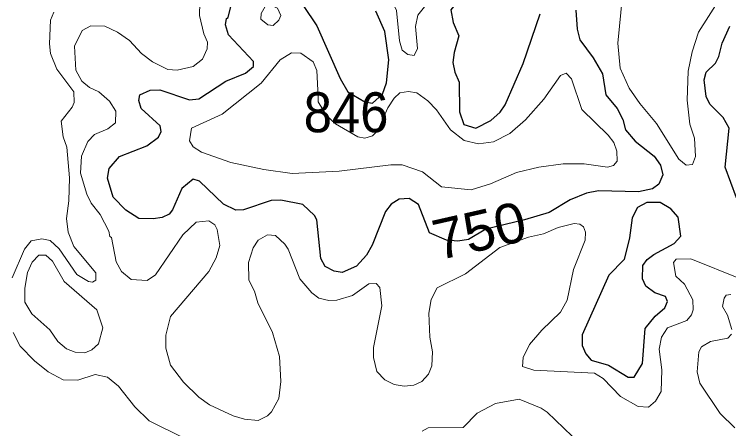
# Model space of a CAD drawing. Extents: x 763.2 to 816.8, y 7896.5 to 7952.7.
# Drawn here: x 783.297 to 786.157, y 7921.048 to 7922.705 of the extents above; entities that cross this region are included whole.
import ezdxf
from ezdxf.enums import TextEntityAlignment as Align

# ---------------------------------------------------------------- set-up
doc = ezdxf.new("R2010")
doc.units = 0
doc.header["$LTSCALE"] = 0.064
doc.layers.add('1', color=7, linetype='Continuous', lineweight=25)
doc.layers.add('2', color=7, linetype='Continuous', lineweight=13)
doc.layers.add('21', color=7, linetype='Continuous')
doc.layers.add('61', color=7, linetype='Continuous')

msp = doc.modelspace()

# ---------------------------------------------------------------- linework, layer by layer
at = {"layer": '1'}
for points in [[(784.5082, 7921.8828), (784.4988, 7921.9003), (784.4517, 7921.9437), (784.3646, 7921.9615), (784.3262, 7921.9601), (784.2144, 7921.923), (784.1847, 7921.9208), (784.1344, 7921.9449), (784.0391, 7922.0369), (784.0137, 7922.045), (783.9686, 7922.0075), (783.9307, 7921.9224), (783.9175, 7921.9053), (783.8888, 7921.8923), (783.8536, 7921.8862), (783.7953, 7921.888), (783.7437, 7921.9213), (783.6931, 7921.9741), (783.6703, 7922.0495), (783.6774, 7922.0887), (783.7181, 7922.1357), (783.828, 7922.1787), (783.8751, 7922.2129), (783.8854, 7922.2362), (783.8811, 7922.2593), (783.8049, 7922.3275), (783.7953, 7922.3598), (783.8001, 7922.3822), (783.8413, 7922.4019), (783.8799, 7922.4021), (783.999, 7922.3629), (784.0358, 7922.3671), (784.1437, 7922.4373), (784.2224, 7922.4697), (784.2552, 7922.4957), (784.2552, 7922.5164), (784.1548, 7922.6226), (784.1422, 7922.6627), (784.1469, 7922.6884), (784.1534, 7922.6926), (784.1795, 7922.8024)], [(785.1868, 7922.8208), (785.0623, 7922.7439), (785.0442, 7922.7229), (785.0536, 7922.6718), (785.0767, 7922.618), (785.0574, 7922.5517)], [(784.4539, 7922.7398), (784.5084, 7922.6585), (784.6014, 7922.4482), (784.6321, 7922.3941), (784.7006, 7922.3552), (784.7305, 7922.3496), (784.7706, 7922.3852), (784.7876, 7922.431), (784.7959, 7922.522), (784.78, 7922.6354), (784.7445, 7922.7167)], [(785.5454, 7922.7219), (785.55, 7922.6455), (785.5611, 7922.603), (785.6145, 7922.5303), (785.652, 7922.4661), (785.6657, 7922.3832), (785.7107, 7922.3281), (785.7335, 7922.2839), (785.7441, 7922.2433), (785.7827, 7922.1976), (785.858, 7922.1369), (785.8835, 7922.102), (785.8935, 7922.0627), (785.8767, 7922.0254), (785.8526, 7922.0063), (785.7954, 7921.9949), (785.6358, 7921.9993), (785.5881, 7921.9889), (785.5226, 7921.9626), (785.4379, 7921.9122), (785.34, 7921.8828), (785.1843, 7921.8456), (785.1158, 7921.8035), (785.0724, 7921.7979), (785.0269, 7921.8018), (784.959, 7921.8305), (784.9151, 7921.9445), (784.8785, 7921.9679), (784.8373, 7921.9648), (784.8064, 7921.9454), (784.7838, 7921.9159), (784.7293, 7921.7809), (784.7078, 7921.7418), (784.6677, 7921.6972), (784.6098, 7921.6725), (784.5774, 7921.6775), (784.5422, 7921.6967), (784.5248, 7921.7275), (784.5082, 7921.8828)], [(785.0574, 7922.5517), (785.0526, 7922.5123), (785.0605, 7922.4736), (785.0785, 7922.4333), (785.079, 7922.3143), (785.097, 7922.2643), (785.1447, 7922.2494), (785.2052, 7922.2806), (785.2416, 7922.3128), (785.2628, 7922.343), (785.3348, 7922.5082), (785.4024, 7922.7062)], [(786.1877, 7921.9714), (786.1423, 7922.0932), (786.1594, 7922.2496), (786.1352, 7922.2916), (786.081, 7922.3449), (786.0663, 7922.3766), (786.0585, 7922.4432), (786.0674, 7922.4729), (786.1041, 7922.509), (786.1176, 7922.5359), (786.1306, 7922.5895), (786.1616, 7922.6578)]]:
    msp.add_lwpolyline(points, dxfattribs=at)
msp.add_lwpolyline([(785.955, 7921.8931), (785.9255, 7921.9271), (785.8823, 7921.9516), (785.8288, 7921.9518), (785.7921, 7921.9319), (785.7705, 7921.8902), (785.7604, 7921.8104), (785.7381, 7921.7246), (785.6771, 7921.6614), (785.5706, 7921.4227), (785.5708, 7921.3799), (785.5851, 7921.3471), (785.6059, 7921.3214), (785.676, 7921.3021), (785.7542, 7921.2536), (785.7786, 7921.2534), (785.8116, 7921.3085), (785.8221, 7921.4478), (785.8622, 7921.4976), (785.9014, 7921.5307), (785.9114, 7921.5567), (785.9039, 7921.5766), (785.8607, 7921.591), (785.825, 7921.6174), (785.8122, 7921.6472), (785.8135, 7921.6998), (785.8304, 7921.7239), (785.8568, 7921.7447), (785.9383, 7921.7882), (785.9655, 7921.8177)], close=True, dxfattribs=at)
at = {"layer": '2'}
for points in [[(785.7263, 7923.1674), (785.7507, 7923.0907), (785.7559, 7922.9792), (785.7461, 7922.8522), (785.7312, 7922.7818), (785.7131, 7922.5893)], [(783.568, 7922.4371), (783.5433, 7922.4817), (783.5389, 7922.5773), (783.5694, 7922.6406), (783.6035, 7922.6585), (783.6604, 7922.6568), (783.7103, 7922.6335), (783.7584, 7922.5997), (783.8066, 7922.5486), (783.8511, 7922.514), (783.9125, 7922.4839), (783.949, 7922.4811), (784.0137, 7922.4959), (784.0501, 7922.5258), (784.07, 7922.5671), (784.0713, 7922.5927), (784.0555, 7922.6269), (784.0385, 7922.7003), (784.0417, 7922.8057)], [(785.7131, 7922.5893), (785.723, 7922.4893), (785.7583, 7922.4091), (785.8006, 7922.3474), (785.8684, 7922.2678), (785.957, 7922.1258), (785.9872, 7922.1015), (786.0119, 7922.1035), (786.0237, 7922.136), (786.0202, 7922.209), (786.0008, 7922.2658), (785.991, 7922.3611), (785.9945, 7922.4775), (786.0106, 7922.555), (786.0367, 7922.6332), (786.1254, 7922.7743)], [(783.4386, 7922.586), (783.4423, 7922.6813), (783.4553, 7922.7132)], [(783.5296, 7922.3337), (783.5371, 7922.3526), (783.5355, 7922.3944), (783.467, 7922.4854), (783.4428, 7922.5474), (783.4386, 7922.586)], [(783.6867, 7921.8126), (783.6804, 7921.8157), (783.6753, 7921.8378), (783.641, 7921.9036), (783.605, 7921.9498), (783.5872, 7921.9851), (783.5619, 7922.0692), (783.5668, 7922.1375), (783.5912, 7922.196), (783.6179, 7922.2242), (783.6724, 7922.247), (783.7023, 7922.2704), (783.7032, 7922.3176), (783.6786, 7922.3574), (783.6351, 7922.3942), (783.5986, 7922.4118), (783.568, 7922.4371)], [(783.2892, 7921.6511), (783.3384, 7921.7661), (783.3652, 7921.799), (783.4073, 7921.8071), (783.4411, 7921.7999), (783.477, 7921.7673), (783.5471, 7921.6643), (783.5947, 7921.6363), (783.611, 7921.6333), (783.6243, 7921.6411), (783.624, 7921.6706), (783.536, 7921.7755), (783.5129, 7921.8337), (783.506, 7921.8877), (783.5158, 7921.9593), (783.5189, 7922.0503), (783.5074, 7922.1737), (783.4925, 7922.215), (783.4845, 7922.2778), (783.5296, 7922.3337)], [(785.9455, 7921.6575), (785.9797, 7921.6258), (786.0135, 7921.563), (786.0151, 7921.5223), (786.0085, 7921.5028), (785.989, 7921.4807), (785.9124, 7921.4507), (785.8884, 7921.4136), (785.879, 7921.3649), (785.8889, 7921.2829), (785.886, 7921.1965), (785.8643, 7921.1582), (785.8358, 7921.1337), (785.7945, 7921.1367), (785.7235, 7921.1757), (785.6545, 7921.2479), (785.6197, 7921.2701), (785.3763, 7921.2814), (785.3321, 7921.2964), (785.3339, 7921.3321), (785.3596, 7921.3841), (785.4089, 7921.4421), (785.4843, 7921.5141), (785.5104, 7921.561), (785.5359, 7921.6846), (785.5818, 7921.8015), (785.5832, 7921.8339), (785.5763, 7921.8548), (785.5615, 7921.8657), (785.5387, 7921.8679), (785.4748, 7921.8515), (785.4163, 7921.8272), (785.3556, 7921.8135), (785.2403, 7921.7723), (785.1038, 7921.6663), (784.9906, 7921.6103), (784.9655, 7921.5648), (784.9572, 7921.509), (784.9605, 7921.4135), (784.9718, 7921.3545), (784.9682, 7921.2984), (784.9552, 7921.2662), (784.9286, 7921.2367), (784.8962, 7921.2222), (784.8575, 7921.2173), (784.8174, 7921.2239), (784.7808, 7921.2427), (784.7489, 7921.2767), (784.7353, 7921.3329), (784.7353, 7921.3717), (784.7681, 7921.5393), (784.7601, 7921.6128), (784.7454, 7921.628), (784.7166, 7921.6266), (784.6508, 7921.5802), (784.5887, 7921.5609), (784.5558, 7921.5605), (784.516, 7921.57), (784.4878, 7921.5913), (784.4405, 7921.6465), (784.3936, 7921.7655), (784.3802, 7921.7858), (784.343, 7921.8198), (784.3114, 7921.8234), (784.2738, 7921.8011), (784.2538, 7921.771), (784.2345, 7921.7125), (784.2358, 7921.6419), (784.2588, 7921.5975), (784.2728, 7921.5503), (784.3314, 7921.4328), (784.3585, 7921.3369), (784.3638, 7921.2362), (784.3556, 7921.168), (784.3274, 7921.1151), (784.3107, 7921.0996), (784.2737, 7921.0809), (784.2182, 7921.0853), (784.173, 7921.0983), (784.0785, 7921.1429), (784.0366, 7921.174), (783.9749, 7921.2331), (783.9222, 7921.3022), (783.9036, 7921.3691), (783.9037, 7921.421), (783.9232, 7921.4956), (784.0761, 7921.6758), (784.106, 7921.7307), (784.1205, 7921.78), (784.1092, 7921.8444), (784.0999, 7921.8634), (784.0761, 7921.8789), (784.0258, 7921.8731), (783.9724, 7921.8231), (783.8629, 7921.6631)], [(783.8629, 7921.6631), (783.8286, 7921.64), (783.7658, 7921.6448), (783.726, 7921.6763), (783.7053, 7921.7152), (783.6867, 7921.8126)], [(786.3459, 7921.6133), (786.2043, 7921.6472), (786.0055, 7921.7262), (785.9472, 7921.725), (785.9365, 7921.712), (785.9455, 7921.6575)], [(786.1652, 7921.5848), (786.1471, 7921.5817), (786.1385, 7921.5698), (786.1322, 7921.5357), (786.152, 7921.5017), (786.1696, 7921.4447)], [(783.9801, 7921.0078), (783.8368, 7921.0784), (783.7804, 7921.1351), (783.714, 7921.2178), (783.6704, 7921.2532), (783.6217, 7921.2648), (783.5519, 7921.2419), (783.4924, 7921.2423), (783.4326, 7921.2744), (783.3783, 7921.3187), (783.3211, 7921.3781), (783.2932, 7921.4319)], [(786.1682, 7921.4252), (786.154, 7921.4098), (786.0841, 7921.3966), (786.0486, 7921.3747), (786.0369, 7921.3543), (786.0306, 7921.2749), (786.0408, 7921.229), (786.1223, 7921.1088), (786.1821, 7921.0508)], [(785.5304, 7921.0181), (785.4298, 7921.114), (785.4058, 7921.1299), (785.3188, 7921.1662), (785.2231, 7921.1485), (785.1495, 7921.1092), (785.0944, 7921.0528), (784.9545, 7921.0511), (784.9293, 7921.0378)]]:
    msp.add_lwpolyline(points, dxfattribs=at)
for points in [[(784.7154, 7922.9731), (784.7139, 7923.044), (784.7491, 7923.0946), (784.9021, 7923.1022), (784.9309, 7923.0883), (784.9516, 7923.0433), (784.949, 7922.9485), (784.9989, 7922.8702), (785.0079, 7922.8442), (785.008, 7922.8078), (784.986, 7922.7699), (784.9445, 7922.7412), (784.9126, 7922.7013), (784.9029, 7922.6562), (784.911, 7922.5675), (784.8976, 7922.5406), (784.8731, 7922.5439), (784.8505, 7922.5618), (784.8389, 7922.598), (784.8272, 7922.7202), (784.7684, 7922.8403), (784.7499, 7922.8646), (784.724, 7922.9324)], [(784.3506, 7922.7295), (784.3297, 7922.7392), (784.3019, 7922.7355), (784.2857, 7922.7084), (784.2842, 7922.6856), (784.3128, 7922.6628), (784.3335, 7922.6602), (784.3566, 7922.6811), (784.3637, 7922.6997)], [(785.3964, 7922.0934), (785.4939, 7922.1062), (785.5789, 7922.1064), (785.6723, 7922.0932), (785.6955, 7922.1002), (785.71, 7922.1171), (785.7096, 7922.1579), (785.6971, 7922.1921), (785.6747, 7922.2219), (785.5696, 7922.3237), (785.5273, 7922.4464), (785.5064, 7922.4695), (785.4831, 7922.4595), (785.4174, 7922.3657), (785.3433, 7922.2822), (785.2803, 7922.2276), (785.2158, 7922.1953), (785.1552, 7922.1869), (785.0981, 7922.1994), (785.0432, 7922.2422), (784.9874, 7922.3228), (784.9533, 7922.3582), (784.9092, 7922.3904), (784.8758, 7922.3956), (784.8407, 7922.3903), (784.8175, 7922.3692), (784.7923, 7922.3307), (784.7519, 7922.24), (784.7316, 7922.2184), (784.701, 7922.21), (784.673, 7922.215), (784.5832, 7922.2671), (784.5471, 7922.2998), (784.5138, 7922.3545), (784.5133, 7922.3752), (784.5083, 7922.4794), (784.4942, 7922.5144), (784.4446, 7922.5496), (784.4066, 7922.55), (784.3622, 7922.5221), (784.2854, 7922.429), (784.1298, 7922.3049), (784.0066, 7922.2496), (783.9991, 7922.1991), (784.0131, 7922.175), (784.0469, 7922.1532), (784.1644, 7922.1115), (784.2965, 7922.0842), (784.4098, 7922.0683), (784.5972, 7922.0768), (784.8042, 7922.103), (784.8496, 7922.103), (784.9311, 7922.0741), (785.008, 7922.0145), (785.1257, 7922.0029), (785.2039, 7922.027), (785.3081, 7922.0715)], [(783.4396, 7921.4425), (783.3676, 7921.5067), (783.34, 7921.5532), (783.3397, 7921.6093), (783.3503, 7921.6722), (783.3692, 7921.7129), (783.3958, 7921.7413), (783.4236, 7921.7412), (783.4501, 7921.718), (783.4964, 7921.6365), (783.6277, 7921.5235), (783.652, 7921.451), (783.6341, 7921.3869), (783.608, 7921.363), (783.58, 7921.3504), (783.541, 7921.354), (783.5065, 7921.3665), (783.4715, 7921.3964)]]:
    msp.add_lwpolyline(points, close=True, dxfattribs=at)

# ---------------------------------------------------------------- texts
at = {"layer": '21', "width": 0.95}
msp.add_text('846', height=0.16, dxfattribs=at).set_placement((784.4558, 7922.2329))
at = {"layer": '61', "width": 1.05}
msp.add_text('750', height=0.16, rotation=12.763, dxfattribs=at).set_placement((785.1764, 7921.7618), align=Align.CENTER)

doc.saveas('drawing.dxf')
